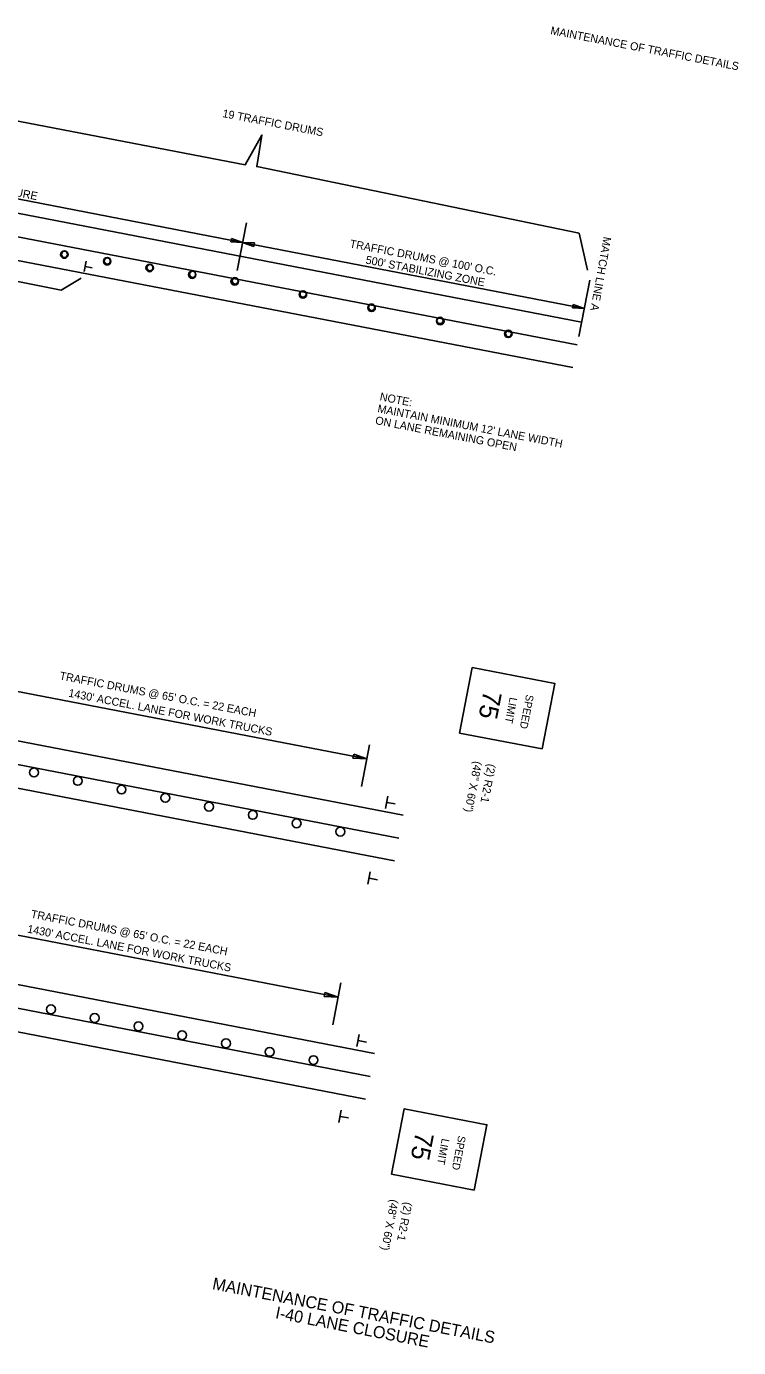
# Model space of a CAD drawing. Extents: x 606969 to 609391, y 416008 to 419486.
# Drawn here: x 607075.7 to 607129, y 419378.5 to 419477.6 of the extents above; entities that cross this region are included whole.
import ezdxf

# ---------------------------------------------------------------- set-up
doc = ezdxf.new("R2010")
doc.units = 0
doc.layers.add('Default', color=7, linetype='Continuous')
doc.layers.add('G-ANNO-TEXT', color=7, linetype='Continuous')

msp = doc.modelspace()

# ---------------------------------------------------------------- linework, layer by layer
at = {"layer": 'Default'}
for p, q in [((607091.877, 419461.373), (607047.495, 419469.94)), ((607047.298, 419468.919), (607117.284, 419455.409)), ((607046.968, 419467.212), (607116.955, 419453.702)), ((607046.639, 419465.505), (607116.625, 419451.995)), ((607092.162, 419462.85), (607091.469, 419459.259)), ((607090.998, 419461.41), (607091.048, 419461.666)), ((607091.877, 419461.373), (607090.998, 419461.41)), ((607091.048, 419461.666), (607091.877, 419461.373)), ((607117.482, 419456.43), (607091.877, 419461.373)), ((607091.877, 419461.373), (607092.755, 419461.336)), ((607092.705, 419461.08), (607091.877, 419461.373)), ((607092.755, 419461.336), (607092.705, 419461.08)), ((607079.993, 419459.2), (607080.141, 419459.968)), ((607080.078, 419459.579), (607080.602, 419459.478)), ((607117.89, 419458.544), (607117.073, 419454.317)), ((607116.603, 419456.467), (607116.653, 419456.723)), ((607117.482, 419456.43), (607116.603, 419456.467)), ((607116.653, 419456.723), (607117.482, 419456.43)), ((607101.182, 419422.666), (607070.832, 419428.525)), ((607070.142, 419424.953), (607103.908, 419418.435)), ((607069.813, 419423.246), (607103.579, 419416.729)), ((607101.387, 419423.725), (607100.782, 419420.591)), ((607100.141, 419422.71), (607100.2, 419423.013)), ((607101.182, 419422.666), (607100.141, 419422.71)), ((607100.2, 419423.013), (607101.182, 419422.666)), ((607069.484, 419421.539), (607103.249, 419415.022)), ((607102.591, 419418.955), (607102.767, 419419.866)), ((607102.692, 419419.406), (607103.314, 419419.286)), ((607101.251, 419413.279), (607101.427, 419414.19)), ((607101.352, 419413.73), (607101.974, 419413.61)), ((607099.028, 419404.809), (607068.677, 419410.668)), ((607067.988, 419407.096), (607101.754, 419400.578)), ((607099.232, 419405.868), (607098.627, 419402.734)), ((607067.659, 419405.389), (607101.424, 419398.872)), ((607097.987, 419404.853), (607098.045, 419405.156)), ((607099.028, 419404.809), (607097.987, 419404.853)), ((607098.045, 419405.156), (607099.028, 419404.809)), ((607067.329, 419403.682), (607101.095, 419397.165)), ((607100.437, 419401.098), (607100.613, 419402.009)), ((607100.538, 419401.549), (607101.159, 419401.429)), ((607099.097, 419395.422), (607099.272, 419396.333)), ((607099.198, 419395.873), (607099.819, 419395.753))]:
    msp.add_line(p, q, dxfattribs=at)
for points in [[(607048.557, 419472.877), (607050.993, 419475.073), (607092.07, 419467.192), (607093.32, 419469.415), (607092.939, 419467.06), (607117.097, 419462.057), (607117.726, 419459.29)], [(607058.433, 419462.471), (607059.441, 419461.583), (607067.065, 419460.111), (607066.977, 419459.295), (607067.387, 419459.98), (607078.276, 419457.808), (607079.766, 419458.701)]]:
    msp.add_lwpolyline(points, dxfattribs=at)
for points in [[(607114.326, 419423.408), (607108.138, 419424.602), (607109.086, 419429.512), (607115.274, 419428.317)], [(607109.235, 419390.339), (607103.047, 419391.534), (607103.995, 419396.443), (607110.183, 419395.249)]]:
    msp.add_lwpolyline(points, close=True, dxfattribs=at)
for centre, radius in [((607078.513, 419460.465), 0.281), ((607078.526, 419460.484), 0.229), ((607081.726, 419459.964), 0.281), ((607081.726, 419459.984), 0.229), ((607084.909, 419459.461), 0.281), ((607084.926, 419459.483), 0.229), ((607088.097, 419458.959), 0.281), ((607088.126, 419458.982), 0.229), ((607091.285, 419458.456), 0.281), ((607091.313, 419458.484), 0.229), ((607091.325, 419458.481), 0.229), ((607096.395, 419457.47), 0.281), ((607096.408, 419457.498), 0.229), ((607101.542, 419456.477), 0.281), ((607101.54, 419456.508), 0.229), ((607106.69, 419455.483), 0.281), ((607106.673, 419455.517), 0.229), ((607111.787, 419454.526), 0.281), ((607111.805, 419454.526), 0.229), ((607076.24, 419421.65), 0.333), ((607079.521, 419421.017), 0.333), ((607082.798, 419420.368), 0.333), ((607086.081, 419419.748), 0.333), ((607089.355, 419419.08), 0.333), ((607092.639, 419418.468), 0.333), ((607095.919, 419417.832), 0.333), ((607099.203, 419417.214), 0.333), ((607077.507, 419403.891), 0.333), ((607080.785, 419403.242), 0.333), ((607084.068, 419402.622), 0.333), ((607087.341, 419401.953), 0.333), ((607090.626, 419401.342), 0.333), ((607093.906, 419400.706), 0.333), ((607097.19, 419400.088), 0.333)]:
    msp.add_circle(centre, radius, dxfattribs=at)

# ---------------------------------------------------------------- texts
for s, height, rotation, p in [('19 TRAFFIC DRUMS', 0.6, 349.07451, (607090.332, 419470.777)), ("900' TAPER FOR LANE CLOSURE", 0.6, 349.07451, (607063.954, 419466.949)), ("TRAFFIC DRUMS @ 100' O.C.", 0.6, 349.07451, (607099.866, 419461.008)), ('MATCH LINE A', 0.6, 259.88043, (607118.925, 419461.836)), ("500' STABILIZING ZONE", 0.6, 349.07451, (607101.063, 419459.796)), ('NOTE:', 0.6, 349.07451, (607102.122, 419449.543)), ("MAINTAIN MINIMUM 12' LANE WIDTH", 0.6, 349.07451, (607101.951, 419448.655)), ('ON LANE REMAINING OPEN', 0.6, 349.07451, (607101.779, 419447.766)), ("TRAFFIC DRUMS @ 65' O.C. = 22 EACH", 0.6, 349.07451, (607078.12, 419428.625)), ("1430' ACCEL. LANE FOR WORK TRUCKS", 0.6, 349.07451, (607078.788, 419427.333)), ('75', 1.3959, 259.07451, (607109.947, 419427.84)), ('LIMIT', 0.5729, 259.07451, (607111.905, 419427.314)), ('SPEED', 0.5729, 259.07451, (607113.139, 419427.527)), ('(48" X 60")', 0.6, 259.07451, (607109.235, 419422.528)), ('(2) R2-1', 0.6, 259.07451, (607110.263, 419422.33)), ("TRAFFIC DRUMS @ 65' O.C. = 22 EACH", 0.6, 349.07451, (607075.966, 419410.768)), ("1430' ACCEL. LANE FOR WORK TRUCKS", 0.6, 349.07451, (607075.702, 419409.655)), ('75', 1.3959, 259.07451, (607104.856, 419394.772)), ('LIMIT', 0.5729, 259.07451, (607106.814, 419394.245)), ('SPEED', 0.5729, 259.07451, (607108.048, 419394.458)), ('(48" X 60")', 0.6, 259.07451, (607102.98, 419389.684)), ('(2) R2-1', 0.6, 259.07451, (607104.008, 419389.486))]:
    msp.add_text(s, height=height, rotation=rotation, dxfattribs=at).set_placement(p)
at = {"layer": 'G-ANNO-TEXT'}
for s, height, p in [('MAINTENANCE OF TRAFFIC DETAILS', 0.6, (607114.916, 419476.988)), ('MAINTENANCE OF TRAFFIC DETAILS', 0.9, (607089.557, 419382.924)), ('I-40 LANE CLOSURE', 0.9, (607094.284, 419380.751))]:
    msp.add_text(s, height=height, rotation=349.07451, dxfattribs=at).set_placement(p)

doc.saveas('drawing.dxf')
